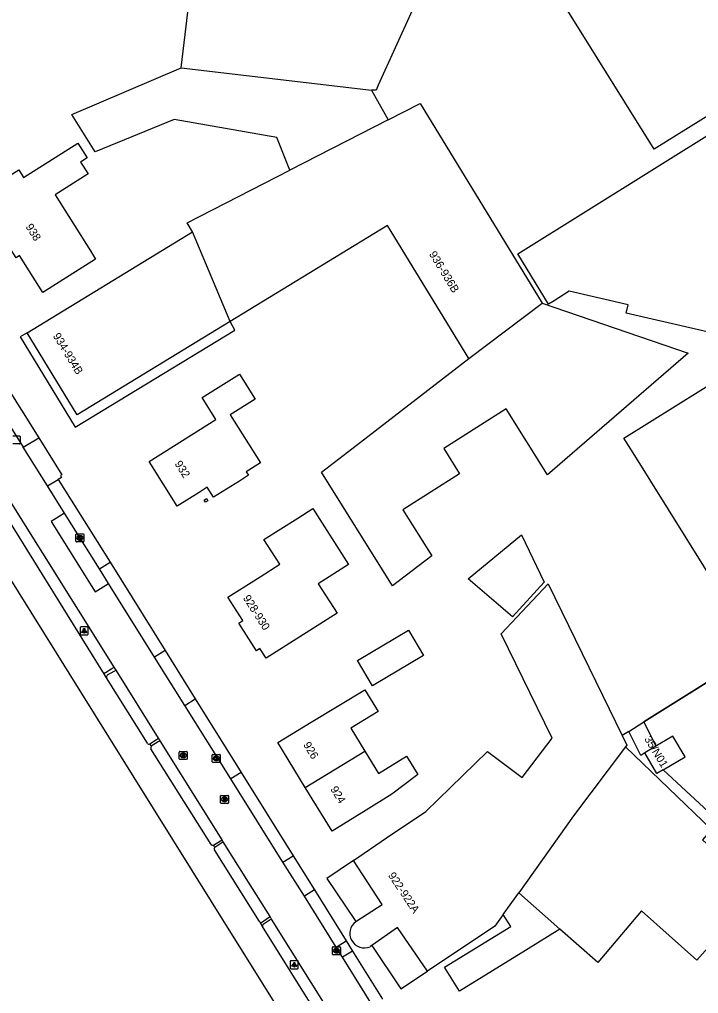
# Model space of a CAD drawing. Extents: x 158461 to 159795, y 387220 to 388672.
# Drawn here: x 158670.3 to 158755, y 387432.5 to 387554.1 of the extents above; entities that cross this region are included whole.
import ezdxf

# ---------------------------------------------------------------- set-up
doc = ezdxf.new("R2010")
doc.units = 0
for name, color, linetype in [('IMGEO_Brandkraan', 7, 'Continuous'), ('IMGEO_Haag', 7, 'Continuous'), ('IMGEO_Hek', 7, 'Continuous'), ('IMGEO_Kolk', 7, 'Continuous'), ('IMGEO_Lichtpunt', 7, 'Continuous'), ('IMGEO_Pand', 7, 'Continuous'), ('IMGEO_Pand_nummerreeks', 7, 'Continuous'), ('IMGEO_Pand_overbouw', 7, 'Continuous'), ('IMGEO_Rijbaan_lokaal_open', 7, 'Continuous'), ('IMGEO_Rijbaan_regionaal_gesloten', 7, 'Continuous'), ('IMGEO_Rioolput', 7, 'Continuous'), ('IMGEO_Voetpad_open', 7, 'Continuous')]:
    doc.layers.add(name, color=color, linetype=linetype)

msp = doc.modelspace()

# ---------------------------------------------------------------- linework, layer by layer
at = {"layer": 'IMGEO_Brandkraan'}
for p, q in [((158695.36, 387456.31), (158695.36, 387457.17)), ((158695.44, 387457.24), (158696.29, 387457.24)), ((158696.36, 387457.17), (158696.36, 387456.31)), ((158696.29, 387456.24), (158695.44, 387456.24)), ((158695.85, 387457.02), (158695.88, 387457.02)), ((158695.87, 387456.46), (158695.85, 387456.46))]:
    msp.add_line(p, q, dxfattribs=at)
for points in [[(158695.36, 387456.31), (158695.36, 387457.17)], [(158695.44, 387457.24), (158696.29, 387457.24)], [(158696.36, 387457.17), (158696.36, 387456.31)], [(158696.29, 387456.24), (158695.44, 387456.24)], [(158695.71, 387456.94), (158695.71, 387456.54), (158695.92, 387456.54)], [(158695.94, 387456.94), (158695.71, 387456.94)], [(158695.89, 387456.86), (158695.84, 387456.86), (158695.84, 387456.78)], [(158695.84, 387456.78), (158695.89, 387456.78)], [(158695.9, 387456.71), (158695.84, 387456.71), (158695.84, 387456.62)], [(158695.84, 387456.62), (158695.9, 387456.62)]]:
    msp.add_lwpolyline(points, dxfattribs=at)
for centre, radius, start, end in [((158695.44, 387457.16), 0.0765, 91.552, 178.448), ((158695.44, 387457.16), 0.0765, 91.552, 178.448), ((158696.29, 387457.16), 0.0765, 1.552, 88.448), ((158696.29, 387457.16), 0.0765, 1.552, 88.448), ((158695.44, 387456.31), 0.0765, 181.552, 268.448), ((158695.44, 387456.31), 0.0765, 181.552, 268.448), ((158695.89, 387456.82), 0.0379, 267.8285, 90.9355), ((158695.9, 387456.67), 0.0404, 269.8759, 90.5077), ((158695.93, 387456.79), 0.251, 268.6676, 293.5347), ((158695.95, 387456.79), 0.145, 59.4692, 91.5367), ((158695.97, 387456.84), 0.0922, 285.5137, 58.1501), ((158695.98, 387456.65), 0.105, 301.3115, 78.989), ((158696.29, 387456.31), 0.0765, 271.552, 358.448), ((158696.29, 387456.31), 0.0765, 271.552, 358.448)]:
    msp.add_arc(centre, radius, start, end, dxfattribs=at)
for centre, major_axis, ratio, start_param, end_param in [((158695.85, 387456.74), (-0.387, 0.002), 0.722429, 4.712389, 7.853982), ((158695.87, 387456.74), (-0.39, 0.002), 0.717154, 1.570796, 4.712389)]:
    msp.add_ellipse(centre, major_axis=major_axis, ratio=ratio, start_param=start_param, end_param=end_param, dxfattribs=at)
at = {"layer": 'IMGEO_Haag'}
for points in [[(158681, 387472.57), (158681.8, 387473.07), (158682.08, 387473.25)], [(158682.32, 387472.88), (158682.03, 387472.71), (158681.21, 387472.24)], [(158686.53, 387463.68), (158687.38, 387464.22), (158687.63, 387464.37)], [(158687.83, 387464.06), (158687.58, 387463.91), (158686.72, 387463.39)], [(158694.48, 387451.01), (158695.36, 387451.56), (158695.56, 387451.69)], [(158695.71, 387451.45), (158695.52, 387451.32), (158694.66, 387450.73)], [(158700.48, 387441.38), (158701.37, 387441.98), (158701.55, 387442.11)], [(158701.74, 387441.8), (158701.55, 387441.68), (158700.67, 387441.11)]]:
    msp.add_lwpolyline(points, dxfattribs=at)
for centre, radius, start, end in [((158680.89, 387472.76), 0.224, 217.1205, 300.935), ((158681.44, 387472.04), 0.309, 137.4744, 199.8355), ((158700.41, 387441.55), 0.191, 219.3686, 292.681), ((158700.81, 387440.94), 0.214, 131.2377, 205.6223)]:
    msp.add_arc(centre, radius, start, end, dxfattribs=at)
at = {"layer": 'IMGEO_Hek'}
for points in [[(158762.31, 387475.26), (158748.22, 387466.41)], [(158746.33, 387465.22), (158745.51, 387464.7)]]:
    msp.add_lwpolyline(points, dxfattribs=at)
at = {"layer": 'IMGEO_Kolk'}
for p, q in [((158669.42, 387502.13), (158670.27, 387502.13)), ((158670.27, 387501.13), (158669.42, 387501.13)), ((158670.35, 387502.06), (158670.35, 387501.21)), ((158677.31, 387488.97), (158677.31, 387489.82)), ((158677.39, 387489.9), (158678.24, 387489.9)), ((158678.24, 387488.9), (158677.39, 387488.9)), ((158677.8, 387489.68), (158677.83, 387489.68)), ((158677.82, 387489.12), (158677.8, 387489.12)), ((158678.31, 387489.82), (158678.31, 387488.97)), ((158694.34, 387461.43), (158694.34, 387462.29)), ((158694.41, 387462.36), (158695.27, 387462.36)), ((158694.83, 387462.14), (158694.85, 387462.14)), ((158695.34, 387462.29), (158695.34, 387461.43)), ((158695.27, 387461.36), (158694.41, 387461.36)), ((158694.85, 387461.58), (158694.82, 387461.58)), ((158709.34, 387437.41), (158709.34, 387438.26)), ((158709.41, 387438.34), (158710.27, 387438.34)), ((158709.83, 387438.12), (158709.85, 387438.12)), ((158710.34, 387438.26), (158710.34, 387437.41)), ((158710.27, 387437.34), (158709.41, 387437.34)), ((158709.85, 387437.56), (158709.82, 387437.56))]:
    msp.add_line(p, q, dxfattribs=at)
for points in [[(158669.42, 387502.13), (158670.27, 387502.13)], [(158670.27, 387501.13), (158669.42, 387501.13)], [(158670.35, 387502.06), (158670.35, 387501.21)], [(158677.31, 387488.97), (158677.31, 387489.82)], [(158677.39, 387489.9), (158678.24, 387489.9)], [(158678.24, 387488.9), (158677.39, 387488.9)], [(158677.63, 387489.6), (158677.76, 387489.6), (158677.76, 387489.45), (158677.89, 387489.6), (158678.05, 387489.6), (158677.91, 387489.45), (158678.06, 387489.2), (158677.91, 387489.2), (158677.82, 387489.36), (158677.76, 387489.29), (158677.76, 387489.2), (158677.63, 387489.2), (158677.63, 387489.6)], [(158678.31, 387489.82), (158678.31, 387488.97)], [(158694.34, 387461.43), (158694.34, 387462.29)], [(158694.41, 387462.36), (158695.27, 387462.36)], [(158694.66, 387462.06), (158694.78, 387462.06), (158694.78, 387461.91), (158694.91, 387462.06), (158695.08, 387462.06), (158694.93, 387461.91), (158695.08, 387461.66), (158694.93, 387461.66), (158694.85, 387461.82), (158694.78, 387461.76), (158694.78, 387461.66), (158694.66, 387461.66), (158694.66, 387462.06)], [(158695.34, 387462.29), (158695.34, 387461.43)], [(158695.27, 387461.36), (158694.41, 387461.36)], [(158709.34, 387437.41), (158709.34, 387438.26)], [(158709.41, 387438.34), (158710.27, 387438.34)], [(158709.66, 387438.04), (158709.78, 387438.04), (158709.78, 387437.88), (158709.91, 387438.04), (158710.08, 387438.04), (158709.93, 387437.89), (158710.08, 387437.64), (158709.93, 387437.64), (158709.85, 387437.8), (158709.78, 387437.73), (158709.78, 387437.64), (158709.66, 387437.64), (158709.66, 387438.04)], [(158710.34, 387438.26), (158710.34, 387437.41)], [(158710.27, 387437.34), (158709.41, 387437.34)]]:
    msp.add_lwpolyline(points, dxfattribs=at)
for centre, start, end in [((158670.27, 387502.06), 1.552, 88.448), ((158670.27, 387502.06), 1.552, 88.448), ((158670.27, 387501.21), 271.552, 358.448), ((158670.27, 387501.21), 271.552, 358.448), ((158677.39, 387489.82), 91.552, 178.448), ((158677.39, 387489.82), 91.552, 178.448), ((158677.39, 387488.97), 181.552, 268.448), ((158677.39, 387488.97), 181.552, 268.448), ((158678.24, 387489.82), 1.552, 88.448), ((158678.24, 387489.82), 1.552, 88.448), ((158678.24, 387488.97), 271.552, 358.448), ((158678.24, 387488.97), 271.552, 358.448), ((158694.42, 387462.28), 91.552, 178.448), ((158694.42, 387462.28), 91.552, 178.448), ((158695.26, 387462.28), 1.552, 88.448), ((158695.26, 387462.28), 1.552, 88.448), ((158694.42, 387461.43), 181.552, 268.448), ((158694.42, 387461.43), 181.552, 268.448), ((158695.26, 387461.43), 271.552, 358.448), ((158695.26, 387461.43), 271.552, 358.448), ((158709.42, 387438.26), 91.552, 178.448), ((158709.42, 387438.26), 91.552, 178.448), ((158710.26, 387438.26), 1.552, 88.448), ((158710.26, 387438.26), 1.552, 88.448), ((158709.42, 387437.41), 181.552, 268.448), ((158709.42, 387437.41), 181.552, 268.448), ((158710.26, 387437.41), 271.552, 358.448), ((158710.26, 387437.41), 271.552, 358.448)]:
    msp.add_arc(centre, 0.0765, start, end, dxfattribs=at)
for centre, major_axis, ratio, start_param, end_param in [((158677.8, 387489.4), (-0.387, 0.002), 0.722429, 4.712389, 7.853982), ((158677.82, 387489.4), (-0.39, 0.002), 0.717154, 1.570796, 4.712389), ((158694.83, 387461.86), (-0.387, 0.002), 0.722429, 4.712389, 7.853982), ((158694.85, 387461.86), (-0.39, 0.002), 0.717154, 1.570796, 4.712389), ((158709.83, 387437.84), (-0.387, 0.002), 0.722429, 4.712389, 7.853982), ((158709.85, 387437.84), (-0.39, 0.002), 0.717154, 1.570796, 4.712389)]:
    msp.add_ellipse(centre, major_axis=major_axis, ratio=ratio, start_param=start_param, end_param=end_param, dxfattribs=at)
at = {"layer": 'IMGEO_Lichtpunt'}
for p, q in [((158677.84, 387478.19), (158677.84, 387477.38)), ((158677.84, 387478.19), (158677.84, 387477.38)), ((158678.75, 387478.29), (158677.94, 387478.29)), ((158678.75, 387478.29), (158677.94, 387478.29)), ((158678.84, 387477.38), (158678.84, 387478.19)), ((158678.84, 387477.38), (158678.84, 387478.19)), ((158677.94, 387477.29), (158678.75, 387477.29)), ((158677.94, 387477.29), (158678.75, 387477.29)), ((158704.08, 387436.49), (158704.08, 387435.69)), ((158704.08, 387436.49), (158704.08, 387435.69)), ((158704.98, 387436.59), (158704.17, 387436.59)), ((158704.98, 387436.59), (158704.17, 387436.59)), ((158705.08, 387435.69), (158705.08, 387436.49)), ((158705.08, 387435.69), (158705.08, 387436.49)), ((158704.17, 387435.59), (158704.98, 387435.59)), ((158704.17, 387435.59), (158704.98, 387435.59))]:
    msp.add_line(p, q, dxfattribs=at)
for points in [[(158678.22, 387477.85), (158678.26, 387477.83), (158678.07, 387477.56), (158678.03, 387477.59), (158678.22, 387477.85)], [(158678.32, 387477.81), (158678.37, 387477.81), (158678.37, 387477.48), (158678.32, 387477.48), (158678.32, 387477.81)], [(158678.43, 387477.83), (158678.47, 387477.85), (158678.66, 387477.59), (158678.62, 387477.56), (158678.43, 387477.83)], [(158704.45, 387436.16), (158704.49, 387436.13), (158704.31, 387435.87), (158704.27, 387435.9), (158704.45, 387436.16)], [(158704.56, 387436.11), (158704.6, 387436.11), (158704.6, 387435.79), (158704.56, 387435.79), (158704.56, 387436.11)], [(158704.67, 387436.13), (158704.7, 387436.16), (158704.89, 387435.89), (158704.85, 387435.87), (158704.67, 387436.13)]]:
    msp.add_lwpolyline(points, dxfattribs=at)
for centre in [(158678.34, 387477.99), (158704.58, 387436.29)]:
    msp.add_circle(centre, 0.0994, dxfattribs=at)
for centre, start, end in [((158677.94, 387478.19), 90, 180), ((158677.94, 387478.19), 90, 180), ((158678.75, 387478.19), 0, 90), ((158678.75, 387478.19), 0, 90), ((158677.94, 387477.38), 180, 270), ((158677.94, 387477.38), 180, 270), ((158678.75, 387477.38), 270, 0), ((158678.75, 387477.38), 270, 360), ((158704.17, 387436.49), 90, 180), ((158704.17, 387436.49), 90, 180), ((158704.98, 387436.49), 0, 90), ((158704.98, 387436.49), 0, 90), ((158704.17, 387435.69), 180, 270), ((158704.17, 387435.69), 180, 270), ((158704.98, 387435.69), 270, 0), ((158704.98, 387435.69), 270, 360)]:
    msp.add_arc(centre, 0.0946, start, end, dxfattribs=at)
at = {"layer": 'IMGEO_Pand'}
for points in [[(158690.46, 387548.09), (158694.68, 387583.58), (158701.91, 387582.72), (158703.69, 387597.67), (158738.94, 387593.48), (158739.16, 387593.96), (158739.52, 387593.71), (158721.42, 387559.96), (158715.06, 387545.94), (158714.78, 387545.3), (158714.23, 387545.33)], [(158749.52, 387537.93), (158738.74, 387555.23), (158752.11, 387563.62), (158751.52, 387564.59), (158754.72, 387566.61), (158755.39, 387565.62), (158781.52, 387581.92), (158792.35, 387564.63), (158749.52, 387537.93)], [(158704.01, 387535.31), (158702.38, 387539.41), (158689.58, 387541.64), (158679.7, 387537.59), (158676.82, 387542.26), (158690.46, 387548.09)], [(158690.46, 387548.09), (158714.23, 387545.33)], [(158714.23, 387545.33), (158716.3, 387541.6)], [(158716.3, 387541.6), (158720.31, 387543.66), (158735.53, 387518.69)], [(158716.3, 387541.6), (158704.01, 387535.31)], [(158769.93, 387521.74), (158766.01, 387519.31), (158764.96, 387521.01), (158763.77, 387520.28), (158762.45, 387522.4), (158759.81, 387520.76), (158758.47, 387514.92), (158759.43, 387514.7), (158759.37, 387514.37), (158754.49, 387515.49), (158746, 387517.44), (158746.25, 387518.51), (158738.89, 387520.2), (158737, 387519.01), (158736.3, 387518.58), (158732.47, 387524.87), (158758.08, 387540.86)], [(158679.12, 387525.26), (158679.78, 387524.22), (158673.2, 387520.05), (158670.29, 387524.65), (158669.85, 387524.38), (158668.42, 387526.65), (158668.85, 387526.92), (158666, 387531.42), (158668.87, 387533.23), (158668.29, 387534.16), (158670.18, 387535.36), (158670.79, 387534.4), (158677.57, 387538.7), (158678.74, 387536.86), (158677.89, 387536.32), (158678.83, 387534.84), (158674.71, 387532.23), (158679.12, 387525.26)], [(158691.85, 387527.62), (158691.22, 387528.76), (158704.01, 387535.31)], [(158726.36, 387511.8), (158716.23, 387528.41), (158696.59, 387516.43)], [(158696.59, 387516.43), (158677.47, 387504.78), (158671.21, 387515.01), (158691.85, 387527.62)], [(158696.59, 387516.43), (158691.85, 387527.62)], [(158735.53, 387518.69), (158753.76, 387512.45), (158736.17, 387497.28), (158731.01, 387505.51), (158723.24, 387500.57), (158725.22, 387497.41), (158718.14, 387492.91), (158721.76, 387487.14), (158716.84, 387483.39), (158707.96, 387497.59), (158712.86, 387501.37), (158726.36, 387511.8)], [(158726.36, 387511.8), (158735.53, 387518.69)], [(158762.31, 387475.26), (158746.87, 387500), (158745.72, 387501.84), (158761.74, 387511.83), (158768.8, 387500.51), (158769.23, 387500.78), (158769.4, 387500.5), (158768.61, 387500), (158767.79, 387499.48), (158770.54, 387494.94), (158769.42, 387494.24), (158771.13, 387491.51), (158776.06, 387483.64), (158762.41, 387475.1)], [(158694.5, 387494.47), (158693.72, 387495.72), (158692.71, 387495.08), (158689.96, 387493.35), (158686.45, 387498.94), (158694.78, 387504.18), (158693.06, 387506.92), (158697.74, 387509.86), (158699.7, 387506.73), (158696.59, 387504.78), (158700.36, 387498.78), (158698.57, 387497.66), (158698.86, 387497.21), (158697.73, 387496.5), (158694.5, 387494.47)], [(158693.49, 387493.84), (158693.31, 387494.12), (158693.6, 387494.3), (158693.78, 387494.02), (158693.49, 387493.84)], [(158709.91, 387479.99), (158705.28, 387477.04), (158701.06, 387474.36), (158700.28, 387475.58), (158699.85, 387475.31), (158697.66, 387478.76), (158698.15, 387479.07), (158696.29, 387481.99), (158700.33, 387484.55), (158702.76, 387486.1), (158700.79, 387489.19), (158705.01, 387491.87), (158706.89, 387493.07), (158711.34, 387486.07), (158707.57, 387483.67), (158709.91, 387479.99)], [(158726.28, 387484.29), (158732.92, 387489.76), (158735.76, 387483.88), (158731.82, 387479.52), (158726.28, 387484.29)], [(158712.26, 387441.47), (158712.4, 387441.56), (158715.55, 387443.62), (158711.96, 387449.12), (158716.1, 387451.92), (158721, 387455.23), (158728.71, 387462.7), (158733.02, 387459.48), (158736.75, 387464.39), (158730.4, 387477.42), (158736.27, 387483.64), (158743.89, 387468.03), (158745.51, 387464.7), (158746.08, 387463.53), (158745.92, 387463.32)], [(158714.36, 387470.91), (158712.48, 387474.08), (158718.84, 387477.87), (158720.72, 387474.7), (158714.36, 387470.91)], [(158705.95, 387458.24), (158702.53, 387463.84), (158706.69, 387466.39), (158713.39, 387470.43), (158715.04, 387467.73), (158711.62, 387465.64), (158713.37, 387462.78)], [(158750.62, 387460.43), (158753.38, 387462.07), (158751.83, 387464.64), (158749.73, 387463.39)], [(158745.92, 387463.32), (158739.44, 387454.69), (158732.6, 387445.08)], [(158745.92, 387463.32), (158756.67, 387452.96), (158755.52, 387451.68), (158755.56, 387451.65), (158762.6, 387445.38), (158754.84, 387436.67), (158747.94, 387442.82), (158742.48, 387436.37), (158737.74, 387440.54)], [(158749.73, 387463.39), (158748.32, 387462.54)], [(158713.37, 387462.78), (158715.07, 387459.99), (158718.59, 387462.14), (158719.99, 387459.85), (158716.75, 387457.4), (158713.55, 387455.4), (158709.31, 387452.75), (158705.95, 387458.24)], [(158705.95, 387458.24), (158713.37, 387462.78)], [(158750.62, 387460.43), (158749.85, 387459.97), (158748.32, 387462.54)], [(158730.67, 387442.37), (158732.6, 387445.08)], [(158732.6, 387445.08), (158737.74, 387440.54)], [(158730.67, 387442.37), (158729.63, 387440.92), (158721.21, 387435.28), (158717.46, 387440.76), (158714.25, 387438.49), (158714.05, 387438.35)], [(158737.74, 387440.54), (158733.43, 387437.88), (158725.18, 387432.81), (158723.34, 387435.8), (158731.59, 387440.87), (158730.67, 387442.37)]]:
    msp.add_lwpolyline(points, dxfattribs=at)
msp.add_arc((158713.32, 387440), 1.81, 125.8324, 293.9337, dxfattribs=at)
at = {"layer": 'IMGEO_Pand_overbouw'}
for points in [[(158696.59, 387516.43), (158677.47, 387504.78), (158671.21, 387515.01), (158670.35, 387514.49), (158677.23, 387503.23), (158697.16, 387515.35)], [(158711.96, 387449.12), (158708.64, 387446.87), (158712.26, 387441.47), (158712.4, 387441.56), (158715.55, 387443.62)], [(158714.25, 387438.49), (158717.89, 387433.07), (158721.21, 387435.28), (158717.46, 387440.76)]]:
    msp.add_lwpolyline(points, close=True, dxfattribs=at)
at = {"layer": 'IMGEO_Rijbaan_lokaal_open'}
for points in [[(158653.96, 387527.57), (158654.38, 387526.89), (158670.75, 387500.72)], [(158673.78, 387495.88), (158670.75, 387500.72)], [(158675.9, 387492.5), (158673.78, 387495.88)], [(158682.08, 387473.25), (158668.74, 387494.59)], [(158675.9, 387492.5), (158674.21, 387491.46), (158679.7, 387482.64), (158681.39, 387483.71)], [(158687.14, 387474.52), (158681.39, 387483.71)], [(158690.93, 387468.46), (158687.14, 387474.52)], [(158748.22, 387466.41), (158762.31, 387475.26)], [(158682.32, 387472.88), (158682.08, 387473.25)], [(158687.63, 387464.37), (158682.32, 387472.88)], [(158696.67, 387459.29), (158690.93, 387468.46)], [(158748.22, 387466.41), (158749.73, 387463.39)], [(158687.83, 387464.06), (158687.63, 387464.37)], [(158695.56, 387451.69), (158687.83, 387464.06)], [(158773.29, 387441.24), (158772.5, 387442.52), (158770.98, 387441.58), (158750.62, 387460.43)], [(158703.16, 387448.92), (158696.67, 387459.29)], [(158695.71, 387451.45), (158695.56, 387451.69)], [(158701.55, 387442.11), (158698.86, 387446.41), (158695.71, 387451.45)], [(158705.83, 387444.65), (158703.16, 387448.92)], [(158709.81, 387438.3), (158705.83, 387444.65)], [(158701.74, 387441.8), (158701.55, 387442.11)], [(158709.06, 387430.09), (158701.74, 387441.8)], [(158710.61, 387437.02), (158709.81, 387438.3)], [(158714.36, 387431.02), (158710.61, 387437.02)]]:
    msp.add_lwpolyline(points, dxfattribs=at)
at = {"layer": 'IMGEO_Rijbaan_regionaal_gesloten'}
for points in [[(158824.18, 387235.99), (158792.36, 387286.93), (158694.26, 387443.97), (158684.57, 387459.46), (158661.98, 387495.7), (158658.09, 387501.91), (158642.29, 387527.16), (158630.02, 387546.72), (158625.56, 387554.19)], [(158680.71, 387472.62), (158680.69, 387472.65), (158667.6, 387493.68)], [(158681.15, 387471.93), (158680.71, 387472.62)], [(158686.25, 387463.74), (158681.15, 387471.93)], [(158686.72, 387463.39), (158686.53, 387463.68)], [(158694.2, 387451.1), (158686.67, 387463.07)], [(158694.66, 387450.73), (158694.48, 387451.01)], [(158700.26, 387441.43), (158700.23, 387441.48), (158694.61, 387450.43)], [(158700.61, 387440.85), (158700.26, 387441.43)], [(158707.71, 387429.45), (158700.61, 387440.85)]]:
    msp.add_lwpolyline(points, dxfattribs=at)
for centre, radius, start, end in [((158686.42, 387463.84), 0.199, 210.6717, 304.6983), ((158687.06, 387463.16), 0.406, 146.4904, 193.6571), ((158694.4, 387451.25), 0.251, 217.1235, 288.9568), ((158694.78, 387450.56), 0.206, 124.3683, 215.6834)]:
    msp.add_arc(centre, radius, start, end, dxfattribs=at)
at = {"layer": 'IMGEO_Rioolput'}
for p, q in [((158690.21, 387461.8), (158690.21, 387462.65)), ((158690.29, 387462.73), (158691.14, 387462.73)), ((158690.7, 387462.51), (158690.73, 387462.51)), ((158691.21, 387462.65), (158691.21, 387461.8)), ((158691.14, 387461.73), (158690.29, 387461.73)), ((158690.72, 387461.95), (158690.7, 387461.95))]:
    msp.add_line(p, q, dxfattribs=at)
for points in [[(158690.21, 387461.8), (158690.21, 387462.65)], [(158690.29, 387462.73), (158691.14, 387462.73)], [(158690.8, 387462.43), (158690.55, 387462.43), (158690.55, 387462.03)], [(158690.55, 387462.03), (158690.67, 387462.03), (158690.67, 387462.19), (158690.68, 387462.19)], [(158690.73, 387462.35), (158690.67, 387462.35), (158690.67, 387462.27)], [(158690.67, 387462.27), (158690.72, 387462.27)], [(158690.73, 387462.16), (158690.8, 387462.03), (158690.94, 387462.03), (158690.88, 387462.15)], [(158691.21, 387462.65), (158691.21, 387461.8)], [(158691.14, 387461.73), (158690.29, 387461.73)]]:
    msp.add_lwpolyline(points, dxfattribs=at)
for centre, radius, start, end in [((158690.29, 387462.65), 0.0765, 91.552, 178.448), ((158690.29, 387462.65), 0.0765, 91.552, 178.448), ((158690.68, 387462.14), 0.0533, 26.0293, 88.6989), ((158690.71, 387462.46), 0.19, 274.7715, 282.9687), ((158690.73, 387462.25), 0.0964, 77.0061, 93.1865), ((158690.75, 387462.31), 0.0378, 276.6634, 79.6772), ((158690.8, 387462.32), 0.109, 350.3612, 89.416), ((158690.8, 387462.32), 0.112, 277.5842, 350.9817), ((158690.78, 387462.1), 0.108, 29.5134, 73.7905), ((158691.14, 387462.65), 0.0765, 1.552, 88.448), ((158691.14, 387462.65), 0.0765, 1.552, 88.448), ((158690.29, 387461.8), 0.0765, 181.552, 268.448), ((158690.29, 387461.8), 0.0765, 181.552, 268.448), ((158691.14, 387461.8), 0.0765, 271.552, 358.448), ((158691.14, 387461.8), 0.0765, 271.552, 358.448)]:
    msp.add_arc(centre, radius, start, end, dxfattribs=at)
for centre, major_axis, ratio, start_param, end_param in [((158690.7, 387462.23), (-0.387, 0.002), 0.722429, 4.712389, 7.853982), ((158690.72, 387462.23), (-0.39, 0.002), 0.717154, 1.570796, 4.712389)]:
    msp.add_ellipse(centre, major_axis=major_axis, ratio=ratio, start_param=start_param, end_param=end_param, dxfattribs=at)
at = {"layer": 'IMGEO_Voetpad_open'}
for points in [[(158655.3, 387528.24), (158655.85, 387528.56), (158663.78, 387516.03), (158672.68, 387501.89)], [(158670.75, 387500.72), (158672.68, 387501.89)], [(158672.68, 387501.89), (158675.56, 387497.27), (158675.4, 387497.19), (158675.53, 387496.95), (158675.12, 387496.7)], [(158673.78, 387495.88), (158675.12, 387496.7)], [(158675.12, 387496.7), (158681.58, 387486.35)], [(158680.26, 387485.52), (158675.9, 387492.5)], [(158680.26, 387485.52), (158681.58, 387486.35)], [(158681.58, 387486.35), (158688.44, 387475.34)], [(158681.39, 387483.71), (158680.26, 387485.52)], [(158688.44, 387475.34), (158687.14, 387474.52)], [(158688.44, 387475.34), (158692.22, 387469.28)], [(158690.93, 387468.46), (158692.22, 387469.28)], [(158692.22, 387469.28), (158697.96, 387460.08)], [(158748.32, 387462.54), (158747.82, 387462.21), (158746.33, 387465.22), (158748.22, 387466.41)], [(158697.96, 387460.08), (158696.67, 387459.29)], [(158697.96, 387460.08), (158704.43, 387449.71)], [(158703.16, 387448.92), (158704.43, 387449.71)], [(158704.43, 387449.71), (158707.09, 387445.43)], [(158707.09, 387445.43), (158706.3, 387444.94), (158705.83, 387444.65)], [(158707.09, 387445.43), (158711.06, 387439.08)], [(158709.81, 387438.3), (158711.06, 387439.08)], [(158711.06, 387439.08), (158711.86, 387437.79)], [(158711.86, 387437.79), (158710.61, 387437.02)], [(158711.86, 387437.79), (158715.6, 387431.79)]]:
    msp.add_lwpolyline(points, dxfattribs=at)

# ---------------------------------------------------------------- texts
at = {"layer": 'IMGEO_Pand_nummerreeks'}
for s, rotation, p in [('938', 302.3549, (158670.99, 387528.25)), ('936-936B', 301.3615, (158721.36, 387524.84)), ('934-934B', 301.4642, (158674.4, 387514.63)), ('932', 302.1628, (158689.6, 387498.66)), ('928-930', 302.4349, (158698.13, 387481.89)), ('35/N01', 301.1486, (158748.22, 387464.29)), ('926', 301.4622, (158705.65, 387463.56)), ('924', 301.4622, (158709.04, 387458.02)), ('922-922A', 303.7355, (158716.24, 387447.24))]:
    msp.add_text(s, height=1, rotation=rotation, dxfattribs=at).set_placement(p)

doc.saveas('drawing.dxf')
